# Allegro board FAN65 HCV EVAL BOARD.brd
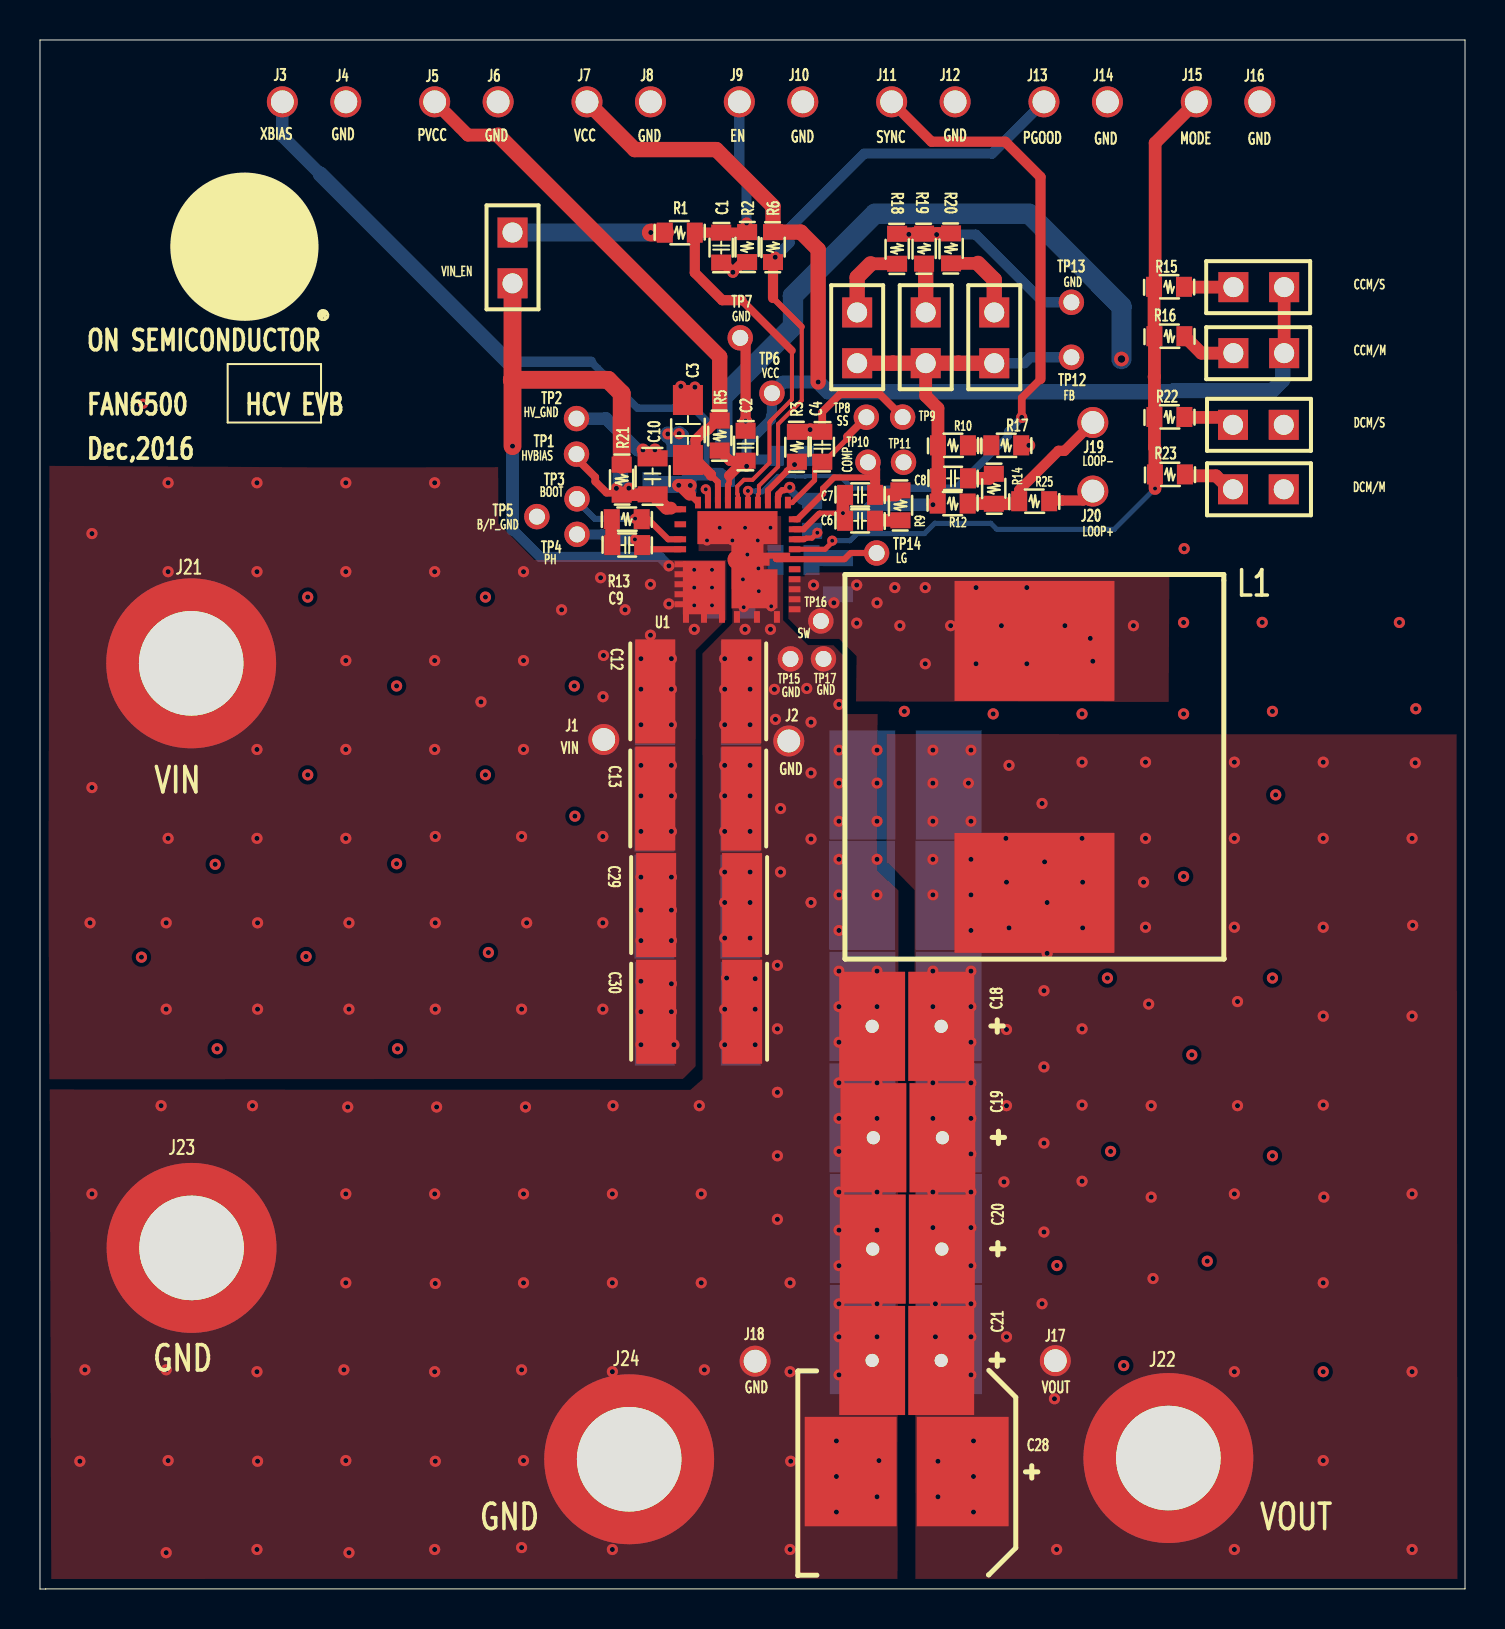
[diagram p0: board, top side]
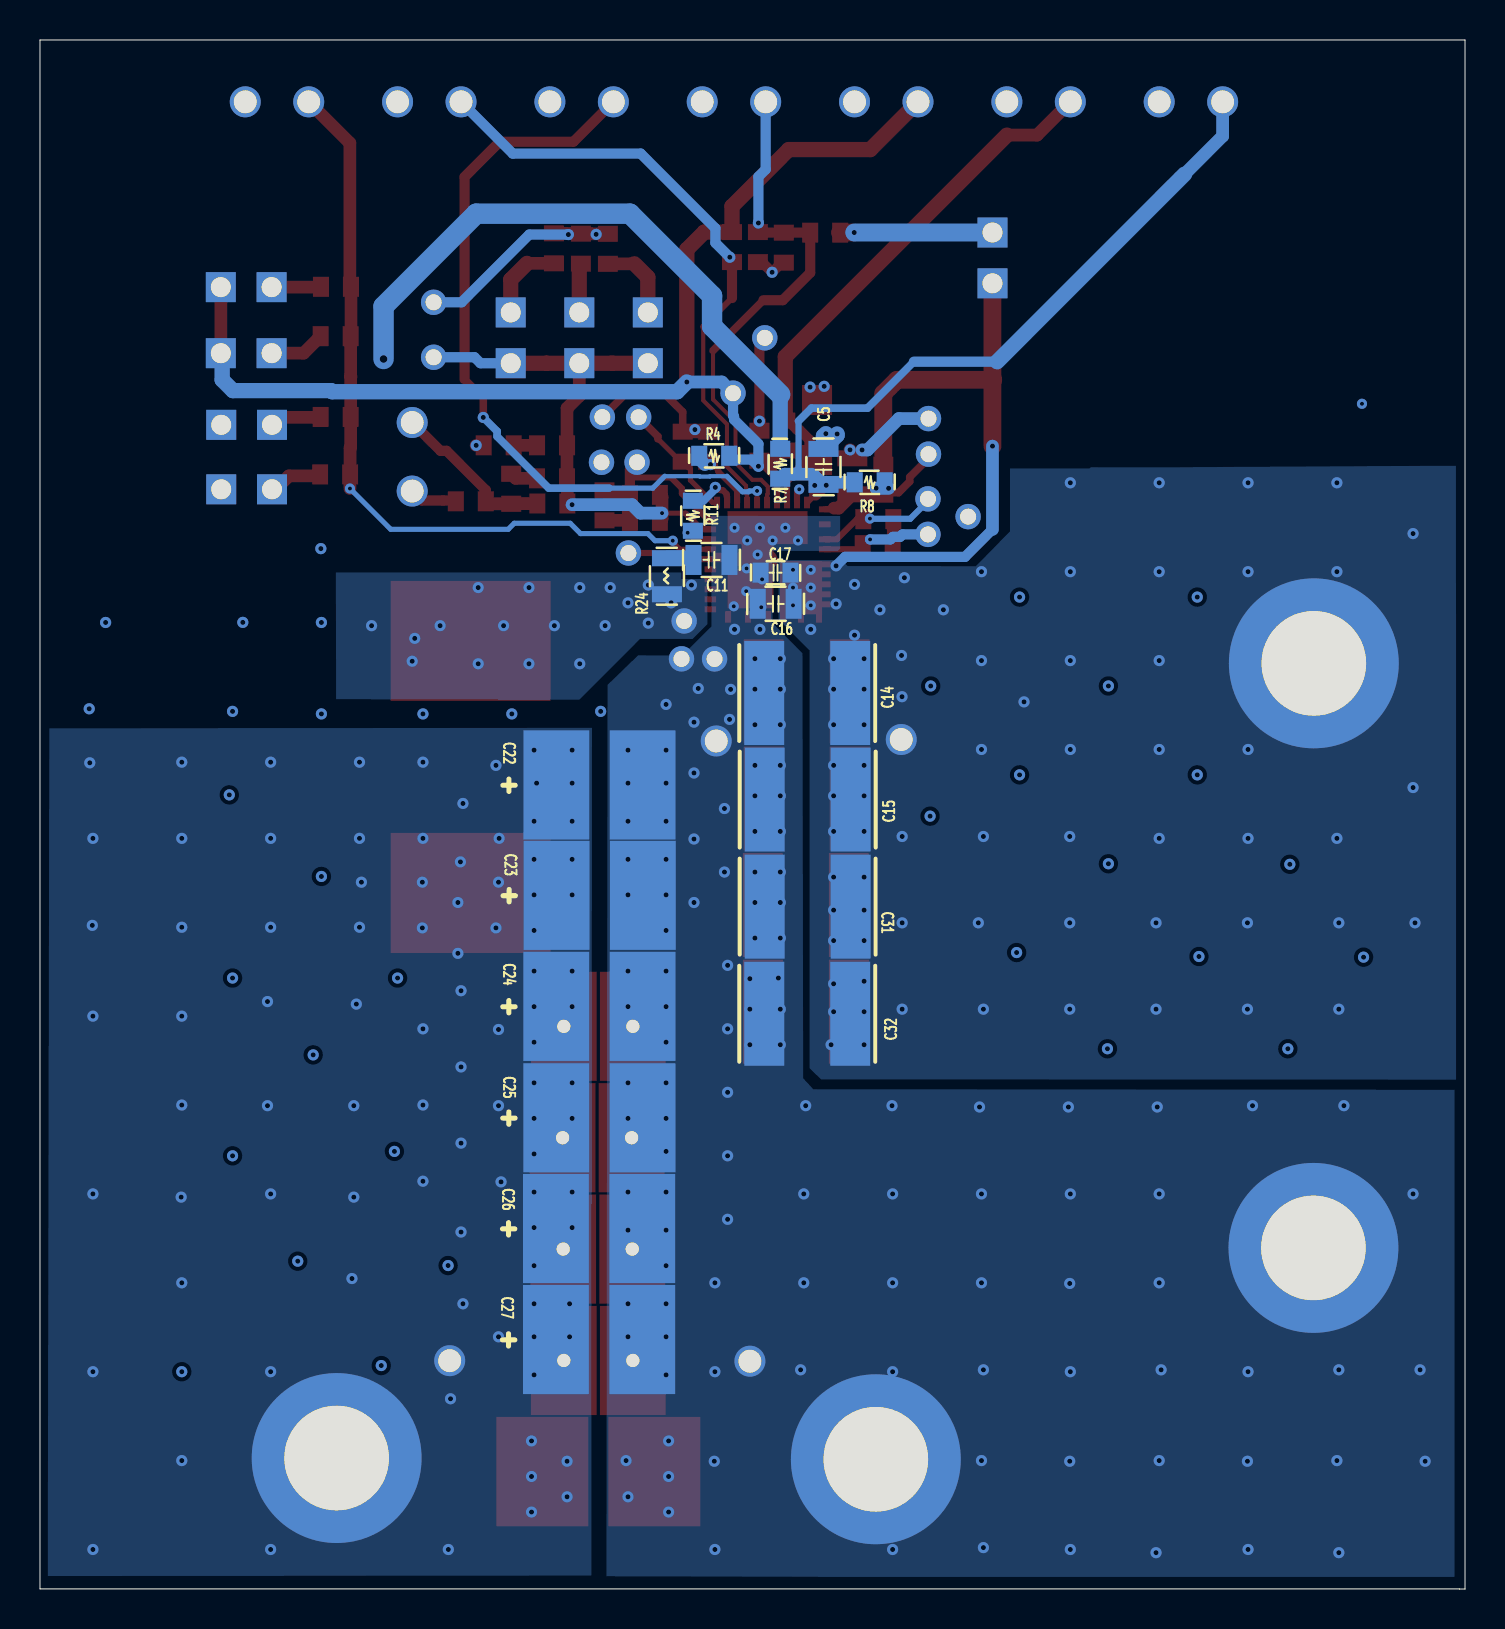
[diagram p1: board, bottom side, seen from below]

Outline 71.29 x 77.46 mm; copper layers: TOP, INNER_1, INNER_2, BOTTOM. Coordinates in mm from the lower left corner of the outline.
Outline path: 0,77.46 0,0.01 0.01,0 0.28,0 0.29,0.01 71.28,0.01 71.29,0.01 71.29,77.46 0,77.46

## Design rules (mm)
constraint set DEFAULT: min track width 0.127, pair gap 0.178

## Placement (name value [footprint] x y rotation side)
C1  220pF  [SM_C_0603]  34.08 66.33 90 top
C2  1uF  [SM_C_0603]  35.3 57.92 270 top
C3  4.7uF  [SMC_1206]  32.41 56.46 90 top
C4  47nF  [SM_C_0603]  39.13 57.87 270 top
C5  0.47uF  [SM_C_0805]  32.09 56.11 270 bottom
C6  b  [SM_C_0603]  41.78 53.42 180 top
C7  c  [SM_C_0603]  41.78 54.71 180 top
C8  e  [SM_C_0603]  46.42 55.54 180 top
C9  0.1uF  [SM_C_0603]  28.63 52.2 0 top
C10  0.47uF  [SM_C_0805]  30.65 55.64 90 top
C11  1-2.2nF  [SM_C_0805]  37.7 51.46 180 bottom
C12  10uF  [SM_C_2220]  32.93 44.89 0 top
C13  10uF  [SM_C_2220]  32.93 39.53 0 top
C14  10uF  [SM_C_2220]  32.91 44.8 0 bottom
C15  10uF  [SM_C_2220]  32.88 39.48 0 bottom
C16  0.47uF  [SM_C_0805]  34.48 49.27 0 bottom
C17  10nF  [SM_C_0603]  33.74 50.82 0 bottom
C18  22uF  [CAP_VOUT_ID_HOLE]  43.36 28.14 180 top
C19  22uF  [CAP_VOUT_ID_HOLE]  43.42 22.57 180 top
C20  22uF  [CAP_VOUT_ID_HOLE]  43.39 17 180 top
C21  22uF  [CAP_VOUT_ID_HOLE]  43.36 11.43 180 top
C22  22uF  [CAP_VOUT_ID]  43.3 40.21 180 bottom
C23  22uF  [CAP_VOUT_ID]  43.29 34.69 180 bottom
C24  22uF  [CAP_VOUT_ID]  43.3 29.13 180 bottom
C25  22uF  [CAP_VOUT_ID]  43.3 23.56 180 bottom
C26  22uF  [CAP_VOUT_ID]  43.32 18.03 180 bottom
C27  22uF  [CAP_VOUT_ID]  43.32 12.47 180 bottom
C28  120uF  [CAP_VOUT_CYL]  43.35 5.87 180 top
C29  10uF  [SM_C_2220]  32.97 34.2 0 top
C30  10uF  [SM_C_2220]  32.97 28.87 0 top
C31  10uF  [SM_C_2220]  32.89 34.12 0 bottom
C32  10uF  [SM_C_2220]  32.91 28.77 0 bottom
J1  VIN  [GOLD_PIN_CONN]  28.2 42.48 180 top
J2  VIN_GND  [GOLD_PIN_CONN]  37.46 42.41 0 top
J3  EXTB  [GOLD_PIN_CONN]  12.12 74.37 0 top
J4  EXTB_GND  [GOLD_PIN_CONN]  15.3 74.37 0 top
J5  PVCC  [GOLD_PIN_CONN]  19.74 74.37 0 top
J6  PVCC_GND  [GOLD_PIN_CONN]  22.92 74.37 0 top
J7  VCC  [GOLD_PIN_CONN]  27.36 74.37 0 top
J8  VCC_GND  [GOLD_PIN_CONN]  30.54 74.37 0 top
J9  EN  [GOLD_PIN_CONN]  34.98 74.37 0 top
J10  EN_GND  [GOLD_PIN_CONN]  38.16 74.37 0 top
J11  SYN  [GOLD_PIN_CONN]  42.6 74.37 0 top
J12  SYN_GND  [GOLD_PIN_CONN]  45.78 74.37 0 top
J13  PG  [GOLD_PIN_CONN]  50.22 74.37 0 top
J14  PG_GND  [GOLD_PIN_CONN]  53.4 74.37 0 top
J15  MODE  [GOLD_PIN_CONN]  57.84 74.37 0 top
J16  MODE_GND  [GOLD_PIN_CONN]  61.02 74.37 0 top
J17  VO  [GOLD_PIN_CONN]  50.79 11.42 0 top
J18  VO_GND  [GOLD_PIN_CONN]  35.77 11.39 0 top
J19  Loop-  [GOLD_PIN_CONN]  52.67 58.33 0 top
J20  Loop+  [GOLD_PIN_CONN]  52.67 54.9 0 top
J21  VIN+  [BANANAPLUG]  7.56 46.29 0 top
J22  VO+  [BANANAPLUG]  56.45 6.55 0 top
J23  VIN-  [BANANAPLUG]  7.58 17.06 0 top
J24  VO-  [BANANAPLUG]  29.47 6.49 0 top
JP1  VIN_EN  [HEADER_2P]  23.64 65.29 180 top
JP2  CCM/S  [HEADER_2P]  62.24 65.1 270 top
JP3  CCM/M  [HEADER_2P]  62.24 61.8 270 top
JP4  17V  [HEADER_2P]  40.88 61.3 180 top
JP5  28V  [HEADER_2P]  44.31 61.3 180 top
JP6  30.5V  [HEADER_2P]  47.74 61.3 180 top
JP7  DCM/S  [HEADER_2P]  59.68 58.21 90 top
JP8  DCM/M  [HEADER_2P]  59.68 54.99 90 top
L1  10uH  [L_19X19MM]  49.75 41.11 270 top
NOREF  -  [unnamed]  10.14 67.22 0 top
R1  825k  [SM_R_0603]  32.76 67.83 180 top
R2  51.1k  [SM_R_0603]  35.37 66.35 90 top
R3  37.5k  [SM_R_0603]  37.86 57.87 270 top
R4  0  [SM_R_0603]  36.81 56.67 0 bottom
R5  1  [SM_R_0603]  34 58.43 270 top
R6  100k  [SM_R_0603]  36.67 67.85 270 top
R7  1  [SM_R_0603]  34.26 57.02 270 bottom
R8  0  [SM_R_0603]  29.03 55.34 0 bottom
R9  RESISTOR  [SM_R_0603]  43.05 54.94 270 top
R10  5.23  [SM_R_0603]  44.92 57.19 0 top
R11  200k  [SM_R_0603]  38.63 52.92 90 bottom
R12  10k  [SM_R_0603]  46.41 54.28 180 top
R13  0  [SM_R_0603]  28.6 53.5 0 top
R14  RESISTOR  [SM_R_0603]  47.72 54.27 90 top
R15  1k  [SM_R_0603]  55.73 65.12 0 top
R16  100k  [SM_R_0603]  55.75 62.65 0 top
R17  464  [SM_R_0603]  47.59 57.19 0 top
R18  1.69k  [SM_R_0603]  42.88 67.77 270 top
R19  412  [SM_R_0603]  44.23 67.78 270 top
R20  348  [SM_R_0603]  45.58 67.79 270 top
R21  1  [SM_R_0603]  29.1 54.72 90 top
R22  1k  [SM_R_0603]  55.75 58.61 0 top
R23  100k  [SM_R_0603]  55.77 55.74 0 top
R24  1-2  [SM_R_0805]  39.92 50.64 90 bottom
R25  10  [SM_R_0603]  48.99 54.39 0 top
TP1  HVBIAS  [08MM_TP]  26.84 56.75 0 top
TP2  HVBIAS_GND  [08MM_TP]  26.84 58.53 0 top
TP3  BOOT  [08MM_TP]  26.87 54.51 0 top
TP4  PH  [08MM_TP]  26.87 52.74 0 top
TP5  B/P_GND  [08MM_TP]  24.86 53.62 0 top
TP6  VCC  [08MM_TP]  36.62 59.8 0 top
TP7  VCC_GND  [08MM_TP]  35.03 62.56 0 top
TP8  SS  [08MM_TP]  41.34 58.59 0 top
TP9  SS_GND  [08MM_TP]  43.16 58.6 0 top
TP10  COMP  [08MM_TP]  41.42 56.34 0 top
TP11  COMP_GND  [08MM_TP]  43.2 56.34 0 top
TP12  FB  [08MM_TP]  51.6 61.59 0 top
TP13  FB_GND  [08MM_TP]  51.6 64.34 0 top
TP14  LG  [08MM_TP]  41.85 51.8 0 top
TP15  LG_GND  [08MM_TP]  37.54 46.51 0 top
TP16  SW  [08MM_TP]  39.06 48.41 0 top
TP17  SW_GND  [08MM_TP]  39.2 46.51 0 top
U1  FAN65  [FAN65_S1]  34.89 51.47 90 top

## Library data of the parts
C1-C11 = CAP NP
C12-C32 = CAP POL
J1-J24 = CON1
JP1-JP8 = SW MAG-SPST/SM
L1 = INDUCTOR
R1-R25 = RESISTOR
TP1-TP17 = TEST POINT
U1 = FAN65_0

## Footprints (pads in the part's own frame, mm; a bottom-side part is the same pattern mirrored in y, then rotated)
08MM_TP
  round 1.272 hole 0.8: 1(0,0)
BANANAPLUG
  round 8.499 hole 5.232: 1(0,0)
CAP_VOUT_CYL
  rect 4.6x5.47 smd: 1(-2.8,0) 2(2.8,0)
CAP_VOUT_ID
  custom 0.824x0.824 smd: 1(-2.159,0) 2(2.159,0)
CAP_VOUT_ID_HOLE
  custom 0.824x0.824 hole 0.66: 1(-1.727,0) 2(1.727,0)
FAN65_S1
  rect 0.58x0.3 smd: 1(-2.86,2.575) 2(-2.86,1.675) 3(-2.86,0.775) 4(-2.86,0.025) 5(-2.86,-0.975) 6(-2.86,-1.975) 17(2.86,-2.525) 18(2.86,-2.025) 19(2.86,-1.525) 20(2.86,-1.025) 21(2.86,-0.525) 22(2.86,-0.025) 23(2.86,0.475) 24(2.86,0.975) 25(2.86,1.475) 26(2.86,1.975)
  rect 0.3x0.58 smd: 7(-2.475,-2.86) 8(-1.975,-2.86) 9(-1.475,-2.86) 10(-0.975,-2.86) 11(-0.475,-2.86) 13(0.525,-2.86) 14(1.025,-2.86) 15(1.525,-2.86) 16(2.025,-2.86) 27(2.525,2.86) 28(1.775,2.86) 29(1.025,2.86) 30(0.525,2.86) 31(-0.225,2.86) 32(-0.725,2.86) 33(-1.225,2.86) 34(-1.725,2.86) 35(-2.225,2.86)
  custom 0.163x0.163 smd: 12(0.03,-1.92)
  custom 0.525x0.525 smd: 36(-1.4,1.68)
  custom 1.001x1.001 smd: 37(0,0)
GOLD_PIN_CONN
  round 1.549 hole 1.143: 1(0,0)
HEADER_2P
  rect 1.5x1.5 hole 1: 1(0,0) 2(0,-2.54)
L_19X19MM
  rect 6x8 smd: 1(-6.3,0) 2(6.3,0)
SM_C_0603
  rect 0.8x1 smd: 1(0,0) 2(1.5,0)
SM_C_0805
  rect 0.8x1.5 smd: 1(-0.9,0) 2(0.9,0)
SM_C_2220
  rect 2x5.2 smd: 1(-2.15,0) 2(2.15,0)
SM_R_0603
  rect 0.8x1 smd: 1(0,0) 2(1.5,0)
SM_R_0805
  rect 0.8x1.5 smd: 1(-0.9,0) 2(0.9,0)
SMC_1206
  rect 1.5x1.5 smd: 1(0,0) 2(3,0)
unnamed
  round 0 smd: 1(1.19,-0.12) 2(-1.105,-0.13)

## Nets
GND: C1.1 C3.2 C5.1 C10.2 C11.2 C12.2 C13.2 C14.2 C15.2 C16.2 C17.2 C18.2 C19.2 C20.2 C21.2 C22.2 C23.2 C24.2 C25.2 C26.2 C27.2 C28.2 C29.2 C30.2 C31.2 C32.2 J2.1 J4.1 J6.1 J10.1 J18.1 J23.1 J24.1 R2.1 TP2.1 TP5.1 TP15.1 TP17.1 U1.4 U1.5 U1.6 U1.37
GND_SIGNAL: C2.1 C4.1 J8.1 J12.1 J14.1 J16.1 JP7.2 JP8.2 R3.1 R11.2 R17.2 R18.1 R19.1 R20.1 TP7.1 TP9.1 TP11.1 TP13.1 U1.18 U1.25
PVCC: C3.1 J5.1 R5.1 U1.24
VCC: C2.2 J7.1 JP2.1 JP3.1 R4.1 R5.2 R6.1 TP6.1 U1.23
VIN: C12.1 C13.1 C14.1 C15.1 C16.1 C17.1 C29.1 C30.1 C31.1 C32.1 J1.1 J21.1 JP1.1 R21.2 U1.1 U1.2 U1.3 U1.31 U1.32 U1.33 U1.34 U1.35 U1.36(VIN_PAD)
BOOT: R13.2 TP3.1 U1.29
COMP: C7.1 R9.1 TP10.1 U1.16
EN: C1.2 J9.1 R1.1 R2.2 U1.22
EXTBIAS: C5.2 J3.1 R7.2 R8.2 U1.26
FB: C6.2 C7.2 C8.2 JP4.1 JP5.1 JP6.1 R10.1 R12.2 TP12.1 U1.15
HVBIAS: C10.1 R8.1 R21.1 TP1.1 U1.27
ILIM: R11.1 U1.14
LG: TP14.1 U1.12
MODE: J15.1 R15.1 R16.1 R22.1 R23.1 U1.13
PGOOD: J13.1 R6.2 U1.20
PH: C9.2 TP4.1 U1.30
RT: R3.2 R4.2 U1.19
SS: C4.2 TP8.1 U1.17
SW: L1.1 R24.1 TP16.1 U1.7 U1.8 U1.9 U1.10
SYNC: J11.1 U1.21
VO: C18.1 C19.1 C20.1 C21.1 C22.1 C23.1 C24.1 C25.1 C26.1 C27.1 C28.1 J17.1 J20.1 J22.1 L1.2 R7.1 R25.2
N381541: JP2.2 R15.2
N381649: JP7.1 R22.2
N381681: JP8.1 R23.2
N382451: J19.1 R12.1 R14.1 R25.1
N382799: C9.1 R13.1
N383173: C6.1 R9.2
N383461: JP3.2 R16.2
N383479: C8.1 R14.2
N383637: JP4.2 R18.2
N383641: JP5.2 R19.2
N383645: JP6.2 R20.2
N383751: R10.2 R17.1
N383951: JP1.2 R1.2
N384211: C11.1 R24.2

Pads without a net: NOREF 1 2; U1 11 28

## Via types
v1: diameter 0.508, hole 0.203, TOP to BOTTOM, 27 vias
v2: diameter 0.559, hole 0.254, TOP to BOTTOM, 364 vias
v3: diameter 0.737, hole 0.381, TOP to BOTTOM, 1 via

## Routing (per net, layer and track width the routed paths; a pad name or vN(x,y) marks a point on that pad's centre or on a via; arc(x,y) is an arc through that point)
GND: length 8.6
  TOP w0.508: R2.1 35.35,66.33 35.15,66.33 v2(34.66,65.84) 34.18,66.33 C1.1
  TOP w0.635: v2(30.77,56.96) 30.77,56.66 C10.2 30.59,56.54 v2(30.16,56.96)
  BOTTOM w0.635: v2(30.16,56.96) 29.89,56.96 28.32,58.53 26.84,58.53 TP2.1
  BOTTOM w0.762: v2(31.97,57.77) 32.09,57.65 C5.1 31.41,57.7 v2(31.41,57.76)
  vias: v1(5.15,59.27) v1(33.37,52.43) v1(34,53.07) v1(34.64,52.43) v1(35.16,50.49) v1(35.2,49.09) v1(35.27,53.07) v1(35.39,51.73) v1(35.91,52.43) v1(35.94,51.03) v1(35.96,49.89) v1(36.54,53.07) v1(36.58,49.14) v2(2,6.39) v2(2.25,10.96) v2(2.6,19.76) v2(5.08,31.6) v2(6.06,24.17) v2(6.31,10.96) v2(6.31,1.82) v2(6.41,6.42) v2(8.76,36.24) v2(8.86,27.02) v2(10.63,24.17) v2(10.85,10.87) v2(10.89,6.39) v2(10.85,1.98) v2(13.31,31.63) v2(13.39,49.6) v2(13.39,40.71) v2(15.2,10.96) v2(15.3,19.76) v2(15.3,15.31) v2(15.3,6.42) v2(15.4,24.1) v2(15.46,1.82) v2(17.84,45.16) v2(17.84,36.27) v2(17.89,27.02) v2(19.74,19.76) v2(19.78,15.28) v2(19.74,10.87) v2(19.78,6.39) v2(19.74,1.98) v2(19.84,24.1) v2(22.28,49.6) v2(22.28,40.71) v2(22.43,31.83) v2(24.09,10.96) v2(24.09,2.07) v2(24.19,19.76) v2(24.19,15.31) v2(24.19,6.42) v2(24.29,24.1) v2(26.73,45.16) v2(26.76,38.65) v2(28.67,24.17) v2(28.63,19.76) v2(28.63,15.31) v2(28.63,10.87) v2(28.63,1.98) v2(32.06,60.14) v2(32.76,60.1) v2(32.98,24.17) v2(33.08,19.76) v2(33.08,15.31) v2(33.24,10.96) v2(34.25,46.52) v2(34.25,45) v2(34.25,43.22) v2(34.25,41.19) v2(34.25,39.66) v2(34.25,37.88) v2(34.25,35.85) v2(34.25,34.33) v2(34.25,32.55) v2(34.25,28.99) v2(34.25,27.22) v2(34.35,30.55) v2(35.27,47.99) v2(35.52,46.52) v2(35.52,45) v2(35.52,43.22) v2(35.52,41.19) v2(35.52,39.66) v2(35.52,37.88) v2(35.52,35.85) v2(35.52,34.33) v2(35.52,32.55) v2(35.78,30.52) v2(35.78,28.99) v2(35.78,27.22) v2(36.54,47.99) v2(36.74,44.99) v2(36.79,43.49) v2(36.89,31.19) v2(36.89,28.01) v2(36.89,24.84) v2(36.89,21.66) v2(36.89,18.49) v2(37.05,39.03) v2(37.05,35.85) v2(37.52,15.31) v2(37.52,10.87) v2(37.56,6.39) v2(37.52,1.98) v2(38.36,45.03) v2(38.57,43.35) v2(38.57,40.81) v2(38.57,37.5) v2(38.57,34.33) v2(39.84,7.4) v2(39.84,5.63) v2(39.84,3.85) v2(39.97,44.23) v2(39.97,41.95) v2(39.97,40.3) v2(39.97,38.39) v2(39.97,36.49) v2(39.97,34.71) v2(39.97,32.93) v2(39.97,30.9) v2(39.97,29.12) v2(39.97,27.34) v2(39.97,25.31) v2(39.97,23.53) v2(39.97,21.88) v2(39.97,19.85) v2(39.97,17.95) v2(39.97,16.17) v2(39.97,14.26) v2(39.97,12.61) v2(39.97,10.71) v2(41.87,41.95) v2(41.87,40.3) v2(41.87,38.39) v2(41.87,36.49) v2(41.87,34.71) v2(41.87,30.9) v2(41.87,29.12) v2(41.87,25.31) v2(41.87,23.53) v2(41.87,19.85) v2(41.87,17.95) v2(41.87,14.26) v2(41.87,12.61) v2(41.87,4.61) v2(41.97,6.42) v2(43.24,43.89) v2(47.68,43.76) v2(50.87,16.17) v2(52.13,43.76) v2(53.4,30.55) v2(53.56,21.88) v2(54.22,11.17) v2(57.21,48.33) v2(57.21,43.76) v2(57.21,35.63) v2(57.62,26.71) v2(58.39,16.39) v2(61.14,48.34) v2(61.65,43.89) v2(61.65,30.55) v2(61.65,21.66) v2(61.82,39.71) v2(64.19,10.87) v2(68,48.33) v2(68.83,44.02)
GND_SIGNAL: length 26.6
  TOP w0.254: v2(37.5,55.09) 37.47,55.05 37.46,55.05 37.37,54.97 37.26,54.97 ; v1(33.31,54.99) 33.42,54.88
  TOP w0.305: U1.18 36.92,54.63 36.94,54.65 36.94,54.75 37.13,54.95 37.24,54.95 37.26,54.97 ; 33.42,54.88 U1.25
  TOP w0.381: C4.1 39.13,58.86 40.02,59.74 42.02,59.74 43.16,58.6 TP9.1
  TOP w0.508: 44.81,67.78 v2(44.86,67.73) 44.91,67.79 ; TP7.1 35.3,62.3 35.3,58.4
  TOP w0.635: C2.1 35.3,58.4 v2(35.3,58.4) ; 38.42,57.87 v2(38.53,57.98) ; 38.42,57.87 R3.1 ; 38.42,57.87 C4.1 ; R17.2 v2(49.47,57.19) ; R18.1 43.74,67.77 43.75,67.78 R19.1 44.81,67.78 ; R20.1 44.91,67.79
  BOTTOM w0.381: v2(37.5,55.09) 37.5,55 38.09,54.42 R11.2
  BOTTOM w0.508: TP13.1 51.59,64.34 50.2,64.34 46.81,67.73 v2(44.86,67.73)
  vias: v2(43.47,67.74) v2(57.24,52.02)
PVCC: length 28.7
  TOP w0.305: U1.24 33.92,55.35 33.59,55.68 33.56,55.68
  TOP w0.381: 32.55,56.59 32.7,56.59
  TOP w0.508: 32.7,56.59 33.56,55.73 33.56,55.68 ; R5.1 33.87,58.43 33.41,57.97 33.3,57.97 32.8,57.46 32.8,56.84 C3.1 32.41,56.55 32.45,56.59 32.55,56.59
  TOP w0.635: J5.1 21.41,72.7 22.92,72.7
  TOP w0.762: 22.92,72.7 34,61.62 R5.1
VCC: length 63
  TOP w0.254: 34.94,56.14 v2(35.35,56.14) 35.35,56.37 ; 34.47,55.27 34.42,55.21
  TOP w0.279: 34.47,55.67 34.47,55.27
  TOP w0.305: 34.42,55.21 U1.23
  TOP w0.381: 35.35,56.37 C2.2
  TOP w0.508: C2.2 34.51,56.42 R5.2 ; 34.94,56.14 34.47,55.67
  TOP w0.635: JP2.1 JP3.1
  TOP w0.762: v2(38.93,60.36) 38.93,66.98 38.06,67.85 R6.1 36.67,69.14 33.83,71.98 29.75,71.98 J7.1
  BOTTOM w0.254: TP6.1 36.62,59.8
  BOTTOM w0.381: 36.62,59.79 TP6.1
  BOTTOM w0.508: R4.1 36.62,56.48 35.68,56.48 v2(35.35,56.14) 35.35,57.26 36.57,58.48 36.57,58.63 36.62,58.68 36.62,59.79
  BOTTOM w0.635: 36.62,59.8 37.18,60.36 v2(38.93,60.36)
  BOTTOM w0.762: v2(38.93,60.36) 39.41,59.87 56.67,59.87 56.73,59.93 61.63,59.93 62.17,60.47 62.17,61.67 62.15,61.69 62.15,61.71 JP3.1
VIN: length 30.3
  TOP w0.889: v2(23.64,57.15) 23.64,60.43 ; 23.64,60.43 JP1.1 ; 23.64,60.43 23.6,60.46 28.42,60.46 29.1,59.78 29.1,56.23 R21.2
  BOTTOM w0.508: v2(31.46,51.16) 31.02,51.61 25.02,51.61 23.64,52.99
  BOTTOM w0.635: v2(23.64,57.15) 23.64,52.99
  vias: v1(32.73,50.97) v1(32.73,50.08) v1(32.73,49.19) v1(33.62,50.97) v1(33.62,50.08) v1(33.62,49.19) v2(2.5,33.31) v2(2.6,52.78) v2(2.6,40.08) v2(6.31,33.31) v2(6.31,28.99) v2(6.41,55.32) v2(6.41,50.87) v2(6.41,37.54) v2(10.85,55.32) v2(10.85,50.87) v2(10.85,41.98) v2(10.85,37.54) v2(10.89,33.31) v2(10.89,28.99) v2(15.3,55.32) v2(15.3,50.87) v2(15.3,46.43) v2(15.3,41.98) v2(15.3,37.54) v2(15.46,33.31) v2(15.46,28.99) v2(19.74,55.32) v2(19.74,50.87) v2(19.74,46.43) v2(19.74,41.98) v2(19.78,37.63) v2(19.78,33.31) v2(19.78,28.99) v2(22.06,44.36) v2(24.09,37.63) v2(24.09,28.99) v2(24.19,50.87) v2(24.19,46.43) v2(24.19,41.98) v2(24.35,33.31) v2(26.09,48.97) v2(28.05,50.57) v2(28.19,46.68) v2(28.16,44.62) v2(28.16,37.63) v2(28.16,33.31) v2(28.16,28.99) v2(29.27,48.97) v2(30.06,46.52) v2(30.06,45) v2(30.06,43.22) v2(30.06,41.19) v2(30.06,39.66) v2(30.06,37.88) v2(30.06,35.6) v2(30.06,33.95) v2(30.06,32.42) v2(30.06,30.39) v2(30.06,28.87) v2(30.06,27.22) v2(30.54,50.24) v2(30.54,47.7) v2(31.46,49.26) v2(31.59,46.52) v2(31.59,45) v2(31.59,43.22) v2(31.59,41.19) v2(31.59,39.66) v2(31.59,37.88) v2(31.59,35.6) v2(31.59,33.95) v2(31.59,32.42) v2(31.59,30.26) v2(31.59,28.87) v2(31.71,27.22) v2(32.73,47.99)
BOOT: length 5.7
  TOP w0.254: 26.87,54.51 TP3.1
  TOP w0.305: R13.2 30.42,53.5 31.43,52.49 U1.29
  BOTTOM w0.305: v1(29.77,53.53) 29.76,53.52 27.76,53.52 26.87,54.41 TP3.1
COMP: length 8.2
  TOP w0.305: 41.65,55.58 39.72,55.58 39.18,55.03 39.18,54.78 37.89,53.49 U1.16
  TOP w0.381: 41.65,55.58 41.78,55.45
  TOP w0.508: TP10.1 41.78,55.99 C7.1
  TOP w0.635: R9.1 42.82,54.71 C7.1
EN: length 26.8
  TOP w0.203: U1.22 34.92,54.72 34.88,54.76 34.88,55.13 35.21,55.47 35.65,55.47 36.49,56.31 36.49,58.33 36.54,58.38 36.54,58.41 37.62,59.48 37.62,61.93
  TOP w0.254: 35.35,67.83 v2(35.35,68.31)
  TOP w0.381: 37.62,61.93 35.1,64.45
  TOP w0.508: R2.2 35.35,67.83 C1.2 34.08,67.83 R1.1 32.76,65.82 34.13,64.45 35.1,64.45
  BOTTOM w0.508: v2(35.35,68.31) 35.35,70.62 34.98,70.99 J9.1
EXTBIAS: length 37.6
  TOP w0.305: 32.5,54.75 U1.26
  TOP w0.635: 32.5,54.75 32.05,55.19 v2(31.95,55.19) 31.96,55.18 v2(32.53,55.18)
  BOTTOM w0.305: 33.6,55.75 33.51,55.84 33.51,55.89 33.5,55.89 33.34,56.05 33.34,58.41
  BOTTOM w0.381: 27.57,61.37 29.89,59.05 32.7,59.05 33.34,58.41
  BOTTOM w0.508: 32.57,55.68 32.64,55.68 32.7,55.75 ; 23.41,61.37 27.57,61.37
  BOTTOM w0.635: 32.7,55.75 34.03,55.75 R7.2 ; J3.1 12.12,72.65 14.03,70.75 ; R8.2 31.97,55.34 C5.2 32.57,55.68
  BOTTOM w0.762: 14.03,70.75 23.41,61.37
FB: length 27.3
  TOP w0.254: v2(44.67,54.22) 44.71,54.22 44.72,54.24 ; 38.96,53.76 39,53.8 v1(40.17,53.8)
  TOP w0.305: 38.96,53.76 38.19,52.99 U1.15
  TOP w0.508: 44.92,57.18 R10.1
  TOP w0.635: R10.1 44.92,59.05 44.31,59.66 JP5.1 ; C6.2 40.17,53.52 v1(40.17,53.8) 40.17,54.61 C7.2 ; v2(44.67,54.22) 44.73,54.28 R12.2 44.91,55.52 C8.2 44.92,57.18
  TOP w0.762: JP4.1 42.67,61.3 JP5.1 45.95,61.3 45.95,61.3 JP6.1
  BOTTOM w0.508: JP6.1 49.25,61.3 49.55,61.59 51.59,61.59 TP12.1
  BOTTOM w0.635: v1(40.17,53.8) 41.25,53.8 41.67,54.22 v2(44.67,54.22)
HVBIAS: length 7.3
  TOP w0.305: U1.27 31.62,53.99 31.56,54.05
  TOP w0.381: 29.1,54.82 R21.1 29,54.82 28.34,54.82 27.78,55.38 27.78,55.6 26.84,56.54 TP1.1
  TOP w0.635: R21.1 30.63,54.72 C10.1 31.34,54.05 31.56,54.05
  BOTTOM w0.635: v2(29.46,55.05) 29.45,55.04 v2(28.84,55.04)
ILIM: length 1.4
  TOP w0.254: v1(38.89,52.82) 38.62,52.55 38.34,52.55 38.33,52.54 38.26,52.54 38.22,52.49
  TOP w0.305: U1.14 38.22,52.49
  BOTTOM w0.254: 38.97,52.74 v1(38.89,52.82)
LG: length 5.2
  TOP w0.305: U1.12 40.25,51.5 40.56,51.81 41.85,51.81 TP14.1
MODE: length 39.8
  TOP w0.254: U1.13 39.28,51.99 39.63,52.35 v1(39.63,52.42)
  TOP w0.635: v1(55.78,55.03) 55.78,55.73 R23.1 55.77,57.06 55.75,57.09 R22.1 55.75,60.63 ; 55.75,60.63 55.73,60.62 ; 55.75,60.63 R16.1 55.73,62.66 R15.1 55.79,65.17 55.79,72.31 J15.1
  BOTTOM w0.254: v1(39.63,52.42) 40.52,52.42 40.88,52.78 44.25,52.78 44.76,53.29 47.56,53.29 47.87,52.99 53.74,52.99 v1(55.78,55.03)
PGOOD: length 30.9
  TOP w0.203: 38.11,63.12 38.11,59.43 36.92,58.25 36.92,56.12 35.97,55.17 35.97,54.77 35.92,54.72 U1.20
  TOP w0.254: v2(36.78,66.6) 36.78,66.46 R6.2
  TOP w0.305: 36.67,64.56 38.11,63.12
  TOP w0.508: R6.2 36.67,64.56
  BOTTOM w0.508: v2(36.78,66.6) 37.5,67.31 37.5,68.04 41.24,71.78 47.64,71.78 J13.1
PH: length 5
  TOP w0.305: C9.2 30.34,51.99 U1.30
  BOTTOM w0.254: 26.87,52.74 TP4.1
  BOTTOM w0.508: v1(29.76,52.48) 28.75,52.48 28.62,52.61 28.26,52.61 28.14,52.74 26.87,52.74
RT: length 3.3
  TOP w0.254: v2(37.75,56.23) 37.65,56.23 37.36,55.93
  TOP w0.305: U1.19 36.42,54.94 37.36,55.88 37.36,55.93
  BOTTOM w0.381: 38.03,56.23 v2(37.75,56.23)
  BOTTOM w0.635: 38.03,56.23 38.31,56.51 R4.2
SS: length 6.1
  TOP w0.254: U1.17 37.63,54.33 38.75,55.44 38.75,55.98 C4.2 39.23,56.37 40.38,57.51
  TOP w0.381: TP8.1 41.34,58.59 40.38,57.64 40.38,57.51
SW:
  vias: v2(38.7,50.2) v2(39.71,49.31) v2(40.86,50.2) v2(40.86,48.3) v2(41.87,49.31) v2(42.76,50.08) v2(43.02,48.17) v2(44.29,50.08) v2(44.29,46.27) v2(45.56,48.17) v2(46.83,50.08) v2(46.83,46.27) v2(48.1,48.17) v2(49.37,50.08) v2(49.37,46.27) v2(51.27,48.17) v2(52.54,47.54) v2(52.67,46.39) v2(54.7,48.17)
SYNC: length 37.9
  TOP w0.203: U1.21 v1(35.42,54.91)
  TOP w0.381: v2(49.11,58.59) 49.11,59.56 50.05,60.5
  TOP w0.508: J11.1 44.6,72.37 48.29,72.37 50.05,70.61 50.05,60.5
  BOTTOM w0.203: 36.92,55.65 37.76,55.65 37.78,55.63 38.27,55.63 38.29,55.65 40.03,55.65
  BOTTOM w0.254: 36.92,55.65 36.14,54.86 35.84,54.86 35.8,54.91 v1(35.42,54.91) ; 40.03,55.65 40.63,55.05 42.82,55.05
  BOTTOM w0.381: v2(49.11,58.59) 48.42,57.89 48.42,57.63 45.84,55.05 42.82,55.05
VO: length 164.2
  TOP w0.508: 51.13,54.43 52.2,54.43 J20.1 ; 51.13,54.43 51.13,54.43 ; 51.13,54.43 50.52,54.43 R25.2
  INNER_2 w0.508: v2(50.13,14.26) 61.13,14.26 65.79,18.92 65.79,41.57 53.75,53.6 53.75,53.82 J20.1
  INNER_2 w1.016: v3(54.1,61.51) 56.61,59 56.61,55.57 56.75,55.43 56.75,54.63 56.69,54.57 67.25,44 67.25,13.64 66.24,12.62 51.52,12.62 50.79,11.9 J17.1
  BOTTOM w0.762: 34.26,59.73 R7.1
  BOTTOM w1.016: v3(54.1,61.51) 54.1,64.14 49.47,68.77 41.77,68.77 37.67,64.67 37.67,63.14 34.26,59.73
  vias: v2(44.67,41.95) v2(44.67,40.3) v2(44.67,38.39) v2(44.67,36.49) v2(44.67,34.71) v2(44.67,30.9) v2(44.67,29.12) v2(44.67,25.31) v2(44.67,23.53) v2(44.67,19.85) v2(44.67,18.07) v2(44.79,14.26) v2(44.79,12.61) v2(44.92,6.39) v2(44.92,4.61) v2(46.45,40.3) v2(46.57,41.95) v2(46.57,38.39) v2(46.57,36.49) v2(46.57,34.71) v2(46.57,32.93) v2(46.57,30.9) v2(46.57,29.12) v2(46.57,27.34) v2(46.57,25.31) v2(46.57,23.53) v2(46.57,21.76) v2(46.57,19.85) v2(46.57,18.07) v2(46.57,16.17) v2(46.57,14.26) v2(46.57,12.61) v2(46.57,10.71) v2(46.7,7.4) v2(46.7,5.63) v2(46.7,3.85) v2(48.22,20.36) v2(48.32,37.54) v2(48.35,35.34) v2(48.35,27.98) v2(48.35,24.17) v2(48.35,12.61) v2(48.48,41.19) v2(48.48,33.06) v2(50.13,39.28) v2(50.26,36.36) v2(50.22,29.92) v2(50.22,26.11) v2(50.22,22.3) v2(50.22,17.85) v2(50.38,34.33) v2(50.38,31.79) v2(50.75,9.51) v2(50.86,1.98) v2(52.13,41.35) v2(52.13,37.54) v2(52.16,35.34) v2(52.16,33.06) v2(52.13,28.01) v2(52.13,24.2) v2(52.13,20.39) v2(55.21,35.34) v2(55.3,41.35) v2(55.3,37.54) v2(55.3,33.09) v2(55.46,29.25) v2(55.59,24.17) v2(55.59,19.6) v2(55.68,15.52) v2(59.75,41.35) v2(59.75,37.54) v2(59.75,33.09) v2(59.75,19.76) v2(59.75,10.87) v2(59.75,1.98) v2(59.91,29.38) v2(59.91,24.17) v2(64.19,41.35) v2(64.19,37.54) v2(64.19,33.09) v2(64.19,28.65) v2(64.19,24.2) v2(64.19,15.31) v2(64.19,6.42) v2(64.23,19.6) v2(68.64,37.54) v2(68.67,33.19) v2(68.64,28.65) v2(68.64,19.76) v2(68.64,10.87) v2(68.64,1.98) v2(68.8,41.31)
N381541: length 2.5
  TOP w0.635: JP2.2 57.25,65.1 R15.2
N381649: length 2.6
  TOP w0.635: JP7.1 59.59,58.3 59.59,58.3 59.3,58.59 57.27,58.59 R22.2
N381681: length 2.7
  TOP w0.635: R23.2 57.35,55.74 57.42,55.66 58.83,55.66 59.44,55.05 59.62,55.05 JP8.1
N382451: length 8.3
  TOP w0.508: R25.1 48.99,54.95 50.95,56.91 51.25,56.91 J19.1
  TOP w0.635: R12.1 47.71,54.28 R14.1 48.86,54.27 R25.1
N382799: length 1.3
  TOP w0.635: C9.1 28.6,52.23 R13.1
N383173: length 1.3
  TOP w0.635: R9.2 41.8,53.44 C6.1
N383461: length 2.8
  TOP w0.635: JP3.2 58.1,61.8 R16.2
N383479: length 1.4
  TOP w0.635: R14.2 47.49,55.54 C8.1
N383637: length 4
  TOP w0.635: R18.2 41.55,66.27
  TOP w0.762: 41.55,66.27 40.88,65.59 JP4.2
N383641: length 2.5
  TOP w0.762: JP5.2 44.31,66.19 R19.2
N383645: length 4.1
  TOP w0.635: R20.2 46.92,66.29
  TOP w0.762: JP6.2 47.74,65.47 46.92,66.29
N383751: length 1.2
  TOP w0.635: R17.1 R10.2
N383951: length 8.4
  TOP w0.635: 30.48,67.83 R1.2
  TOP w0.889: v2(30.56,67.83) 31.25,67.83 R1.2
  BOTTOM w0.889: JP1.2 v2(30.56,67.83)
N384211: length 1.4
  BOTTOM w0.762: R24.2 38.68,51.54 C11.1

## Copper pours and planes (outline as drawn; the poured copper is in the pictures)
GND on TOP: 40.32,43.75 41.9,43.75 41.86,37.72 41.87,35.92 42.95,34.93 42.9,0.51 0.56,0.5 0.49,24.98 32.54,24.96 33.15,25.5 33.14,46.78 34.64,48.3 34.65,51.9 32.95,51.9 32.95,53.66 34.64,53.65 36.36,53.65 37.07,53.65 37.08,51.92 36.35,51.92 36.36,50.88 36.5,50.73 37.18,50.72 37.18,48.44 38.42,47.2 39.69,47.19 40.31,46.55
GND on BOTTOM: 42.95,0.64 42.9,45.21 41.37,46.69 39.16,46.69 37.7,48.14 37.7,53.66 31.26,53.66 31.26,51.91 34.65,51.91 34.64,51.38 34.64,48.31 33.14,46.79 33.11,25.54 32.6,24.99 0.53,24.96 0.53,0.6 30.83,0.6
GND on INNER_1: 0.37,0.44 0.37,50.2 37.29,50.22 37.27,48.95 37.26,48.37 38.54,47.22 39.79,47.24 40.65,46.38 40.66,44.18 56.72,44.18 56.72,50.2 70.96,50.2 70.96,0.44
GND on INNER_2: 0.5,0.5 0.5,77.14 70.82,77.14 70.82,0.5 ; 2 cut-outs
GND_SIGNAL on INNER_1: 0.35,50.93 0.35,77.21 71,77.21 71,50.93 ; 3 cut-outs
VIN on TOP: 32.16,25.5 32.8,26.14 32.8,46.94 34.33,48.47 34.33,51.44 34.32,51.45 24.73,51.46 22.93,53.29 22.92,56.1 14.89,56.08 0.47,56.16 0.43,34.48 0.47,25.49
VIN on BOTTOM: 0.45,25.47 32.21,25.48 32.79,26.04 32.79,46.93 34.33,48.48 34.33,51.45 31.18,51.45 30.88,51.15 24.48,51.15 24.16,51.46 22.76,52.89 22.76,56.03 18.77,56.04 18.71,56.1 16.49,56.09 14.9,56.09 14.89,56.09 0.46,56.17 0.45,48.77 0.45,48.77
SW on TOP: 37.44,50.67 37.44,48.52 38.45,47.51 39.98,47.51 40.85,46.65 40.82,44.38 56.46,44.36 56.5,50.83 38.38,50.83 38.22,50.67
SW on BOTTOM: 37.88,50.67 37.88,48.27 38.64,47.51 41.26,47.51 44.31,44.47 56.47,44.49 56.49,50.83 38.38,50.83 38.22,50.67
VO on TOP: 43.69,42.75 42.34,42.75 42.36,36.29 42.45,36.29 43.75,34.95 43.79,0.5 70.91,0.5 70.87,42.74
VO on BOTTOM: 43.67,43.06 43.71,0.67 70.9,0.65 70.82,43.04

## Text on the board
Ref Des/Silkscreen Top: VIN_EN | B/P_GND | HVBIAS | HV_GND | BOOT | PH | GND | VCC | SW | SS | LG | FB | LOOP- | LOOP+ | DCM/M | CCM/S | CCM/M | DCM/S | COMP | XBIAS | PVCC | VIN | EN | SYNC | PGOOD | VOUT | MODE | Dec,2016 | ON SEMICONDUCTOR | FAN6500     HCV EVB
